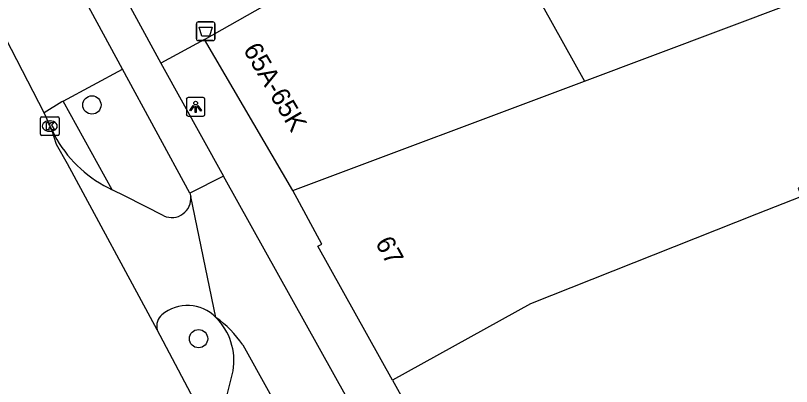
# Model space of a CAD drawing. Extents: x 161882 to 162509, y 381687 to 382379.
# Drawn here: x 162064.06 to 162105.57, y 381964.85 to 381984.7 of the extents above; entities that cross this region are included whole.
import ezdxf

# ---------------------------------------------------------------- set-up
doc = ezdxf.new("R2010")
doc.units = 0
for name, color, linetype in [('IMGEO_Afvalbak', 7, 'Continuous'), ('IMGEO_Boom', 7, 'Continuous'), ('IMGEO_Fietspad_gesloten', 7, 'Continuous'), ('IMGEO_Fietspad_open', 7, 'Continuous'), ('IMGEO_Kolk', 7, 'Continuous'), ('IMGEO_Lichtpunt', 7, 'Continuous'), ('IMGEO_Pand', 7, 'Continuous'), ('IMGEO_Pand_nummerreeks', 7, 'Continuous'), ('IMGEO_Parkeervlak_open', 7, 'Continuous'), ('IMGEO_Rijbaan_lokaal_gesloten', 7, 'Continuous'), ('IMGEO_Voetpad_open', 7, 'Continuous')]:
    doc.layers.add(name, color=color, linetype=linetype)

msp = doc.modelspace()

# ---------------------------------------------------------------- linework, layer by layer
at = {"layer": 'IMGEO_Afvalbak'}
for p, q in [((162073.833, 381984.36), (162074.623, 381984.36)), ((162074.623, 381984.36), (162073.833, 381984.36)), ((162073.733, 381983.46), (162073.733, 381984.26)), ((162073.733, 381984.26), (162073.733, 381983.46)), ((162074.723, 381984.26), (162074.723, 381983.46)), ((162074.723, 381983.46), (162074.723, 381984.26)), ((162074.623, 381983.36), (162073.833, 381983.36)), ((162073.833, 381983.36), (162074.623, 381983.36))]:
    msp.add_line(p, q, dxfattribs=at)
msp.add_lwpolyline([(162073.876, 381984.074), (162074.58, 381984.074), (162074.431, 381983.604), (162074.025, 381983.604), (162073.876, 381984.074)], dxfattribs=at)
for centre, start, end in [((162073.833, 381984.26), 90, 180), ((162073.833, 381984.26), 90, 180), ((162074.623, 381984.26), 0, 90), ((162074.623, 381984.26), 360, 90), ((162073.833, 381983.46), 180, 270), ((162073.833, 381983.46), 180, 270), ((162074.623, 381983.46), 270, 0), ((162074.623, 381983.46), 270, 0)]:
    msp.add_arc(centre, 0.1, start, end, dxfattribs=at)
at = {"layer": 'IMGEO_Boom'}
for centre in [(162068.144, 381979.919), (162073.85, 381967.407)]:
    msp.add_circle(centre, 0.489, dxfattribs=at)
at = {"layer": 'IMGEO_Fietspad_gesloten'}
for points in [[(162064.377, 381995.878), (162067.605, 381989.931), (162071.825, 381982.158)], [(162069.775, 381981.832), (162062.41, 381995.394)], [(162073.393, 381975.201), (162069.775, 381981.832)], [(162071.825, 381982.158), (162075.194, 381976.109)], [(162075.194, 381976.109), (162073.393, 381975.201)]]:
    msp.add_lwpolyline(points, dxfattribs=at)
at = {"layer": 'IMGEO_Fietspad_open'}
for points in [[(162087.64, 381953.76), (162075.194, 381976.109)], [(162073.393, 381975.201), (162073.43, 381975.024)], [(162076.214, 381967.086), (162084.266, 381952.579), (162111.528, 381904.042)]]:
    msp.add_lwpolyline(points, dxfattribs=at)
msp.add_arc((162071.422, 381963.8), 5.811, 34.4385, 54.7303, dxfattribs=at)
at = {"layer": 'IMGEO_Kolk'}
for p, q in [((162065.39, 381978.361), (162065.39, 381979.213)), ((162065.465, 381979.287), (162066.317, 381979.287)), ((162065.878, 381979.067), (162065.903, 381979.067)), ((162066.391, 381979.213), (162066.391, 381978.361)), ((162065.901, 381978.507), (162065.876, 381978.507)), ((162066.317, 381978.287), (162065.465, 381978.287))]:
    msp.add_line(p, q, dxfattribs=at)
for points in [[(162065.39, 381978.361), (162065.39, 381979.213)], [(162065.465, 381979.287), (162066.317, 381979.287)], [(162065.711, 381978.987), (162065.834, 381978.987), (162065.834, 381978.836), (162065.964, 381978.987), (162066.128, 381978.987), (162065.982, 381978.836), (162066.135, 381978.587), (162065.983, 381978.587), (162065.898, 381978.751), (162065.834, 381978.684), (162065.834, 381978.587), (162065.711, 381978.587), (162065.711, 381978.987)], [(162066.391, 381979.213), (162066.391, 381978.361)], [(162066.317, 381978.287), (162065.465, 381978.287)]]:
    msp.add_lwpolyline(points, dxfattribs=at)
for centre, start, end in [((162065.467, 381979.211), 91.552, 178.448), ((162065.467, 381979.211), 91.552, 178.448), ((162066.315, 381979.211), 1.552, 88.448), ((162066.315, 381979.211), 1.552, 88.448), ((162065.467, 381978.363), 181.552, 268.448), ((162065.467, 381978.363), 181.552, 268.448), ((162066.315, 381978.363), 271.552, 358.448), ((162066.315, 381978.363), 271.552, 358.448)]:
    msp.add_arc(centre, 0.0765, start, end, dxfattribs=at)
for centre, major_axis, ratio, start_param, end_param in [((162065.877, 381978.787), (-0.387, 0.002), 0.722429, 4.712389, 7.853982), ((162065.902, 381978.787), (-0.39, 0.002), 0.717154, 1.570796, 4.712389)]:
    msp.add_ellipse(centre, major_axis=major_axis, ratio=ratio, start_param=start_param, end_param=end_param, dxfattribs=at)
at = {"layer": 'IMGEO_Lichtpunt'}
for p, q in [((162073.197, 381980.22), (162073.197, 381979.413)), ((162073.197, 381980.22), (162073.197, 381979.413)), ((162074.099, 381980.315), (162073.291, 381980.315)), ((162074.099, 381980.315), (162073.291, 381980.315)), ((162074.193, 381979.413), (162074.193, 381980.22)), ((162074.193, 381979.413), (162074.193, 381980.22)), ((162073.291, 381979.319), (162074.099, 381979.319)), ((162073.291, 381979.319), (162074.099, 381979.319))]:
    msp.add_line(p, q, dxfattribs=at)
for points in [[(162073.571, 381979.884), (162073.61, 381979.856), (162073.422, 381979.594), (162073.384, 381979.621), (162073.571, 381979.884)], [(162073.673, 381979.836), (162073.72, 381979.836), (162073.72, 381979.514), (162073.673, 381979.514), (162073.673, 381979.836)], [(162073.783, 381979.856), (162073.821, 381979.883), (162074.008, 381979.621), (162073.969, 381979.593), (162073.783, 381979.856)]]:
    msp.add_lwpolyline(points, dxfattribs=at)
msp.add_circle((162073.696, 381980.018), 0.0994, dxfattribs=at)
for centre, start, end in [((162073.291, 381980.22), 90, 180), ((162073.291, 381980.22), 90, 180), ((162074.099, 381980.22), 0, 90), ((162074.099, 381980.22), 0, 90), ((162073.291, 381979.413), 180, 270), ((162073.291, 381979.413), 180, 270), ((162074.099, 381979.413), 270, 0), ((162074.099, 381979.413), 270, 360)]:
    msp.add_arc(centre, 0.0946, start, end, dxfattribs=at)
at = {"layer": 'IMGEO_Pand'}
for points in [[(162094.493, 381981.199), (162124.179, 381992.364), (162125.323, 381987.847), (162115.138, 381984.016), (162116.818, 381979.55), (162112.686, 381977.996), (162105.938, 381975.458), (162106.111, 381975.02)], [(162074.163, 381983.415), (162084.06, 381989.037), (162084.239, 381988.715), (162088.878, 381991.295)], [(162088.878, 381991.295), (162094.493, 381981.199)], [(162078.888, 381975.33), (162074.163, 381983.415)], [(162078.888, 381975.33), (162094.493, 381981.199)], [(162084.224, 381965.182), (162080.234, 381972.356), (162080.448, 381972.475), (162078.888, 381975.33)], [(162106.111, 381975.02), (162103.707, 381974.071), (162091.602, 381969.28), (162084.224, 381965.182)], [(162084.224, 381965.182), (162089.877, 381955.018)]]:
    msp.add_lwpolyline(points, dxfattribs=at)
at = {"layer": 'IMGEO_Parkeervlak_open'}
msp.add_lwpolyline([(162110.128, 381903.311), (162108.772, 381905.652), (162107.884, 381905.166), (162102.118, 381915.454), (162102.985, 381915.921), (162101.417, 381918.762), (162100.535, 381918.293), (162094.757, 381928.54), (162095.649, 381929.029), (162094.05, 381931.846), (162093.19, 381931.352), (162087.448, 381941.624), (162088.219, 381942.206), (162086.738, 381944.939), (162085.861, 381944.447), (162080.108, 381954.721), (162080.998, 381955.203), (162079.42, 381958.024), (162078.528, 381957.526), (162075.168, 381963.546), (162075.702, 381965.694)], dxfattribs=at)
msp.add_arc((162072.473, 381966.221), 3.272, 350.727, 45.2358, dxfattribs=at)
at = {"layer": 'IMGEO_Rijbaan_lokaal_gesloten'}
for points in [[(162065.582, 381979.503), (162062.076, 381986.301), (162058.206, 381993.875), (162057.987, 381994.304)], [(162065.992, 381978.592), (162065.582, 381979.503)], [(162071.636, 381967.886), (162066.835, 381976.766), (162066.256, 381977.793), (162065.992, 381978.592)], [(162065.992, 381978.592), (162066.265, 381978.073)], [(162071.998, 381973.982), (162069.927, 381975.036), (162069.236, 381975.383)], [(162074.777, 381968.544), (162073.43, 381975.024)], [(162107.811, 381901.826), (162076.565, 381958.577), (162071.636, 381967.886)]]:
    msp.add_lwpolyline(points, dxfattribs=at)
for centre, radius, start, end in [((162072.015, 381981.438), 6.662, 210.337, 245.3464), ((162072.42, 381974.907), 1.017, 245.498, 6.5853), ((162073.252, 381967.033), 2.147, 44.7404, 129.3923), ((162072.448, 381968.074), 0.833, 132.1236, 193.0227)]:
    msp.add_arc(centre, radius, start, end, dxfattribs=at)
at = {"layer": 'IMGEO_Voetpad_open'}
for points in [[(162074.163, 381983.415), (162071.825, 381982.158)], [(162066.606, 381980.116), (162069.775, 381981.832)], [(162066.606, 381980.116), (162066.538, 381980.079), (162065.582, 381979.503)], [(162069.236, 381975.383), (162066.606, 381980.116)]]:
    msp.add_lwpolyline(points, dxfattribs=at)

# ---------------------------------------------------------------- texts
at = {"layer": 'IMGEO_Pand_nummerreeks'}
for s, rotation, p in [('65A-65K', 300.3035, (162076.214, 381982.878)), ('67', 298.6534, (162083.283, 381972.542))]:
    msp.add_text(s, height=1, rotation=rotation, dxfattribs=at).set_placement(p)

doc.saveas('drawing.dxf')
